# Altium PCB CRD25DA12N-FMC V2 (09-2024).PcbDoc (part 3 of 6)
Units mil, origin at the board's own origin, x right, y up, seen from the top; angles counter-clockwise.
Board outline 8000 x 8000 mil, 6 copper layers (Top Layer, Layer 2, Layer 3, Layer 4, Layer 5, Bottom Layer), stack 91 mil thick; 602 components, 333 nets, 1670 pads, 639 vias.
Unrouted connection lines stored in the file: 1.
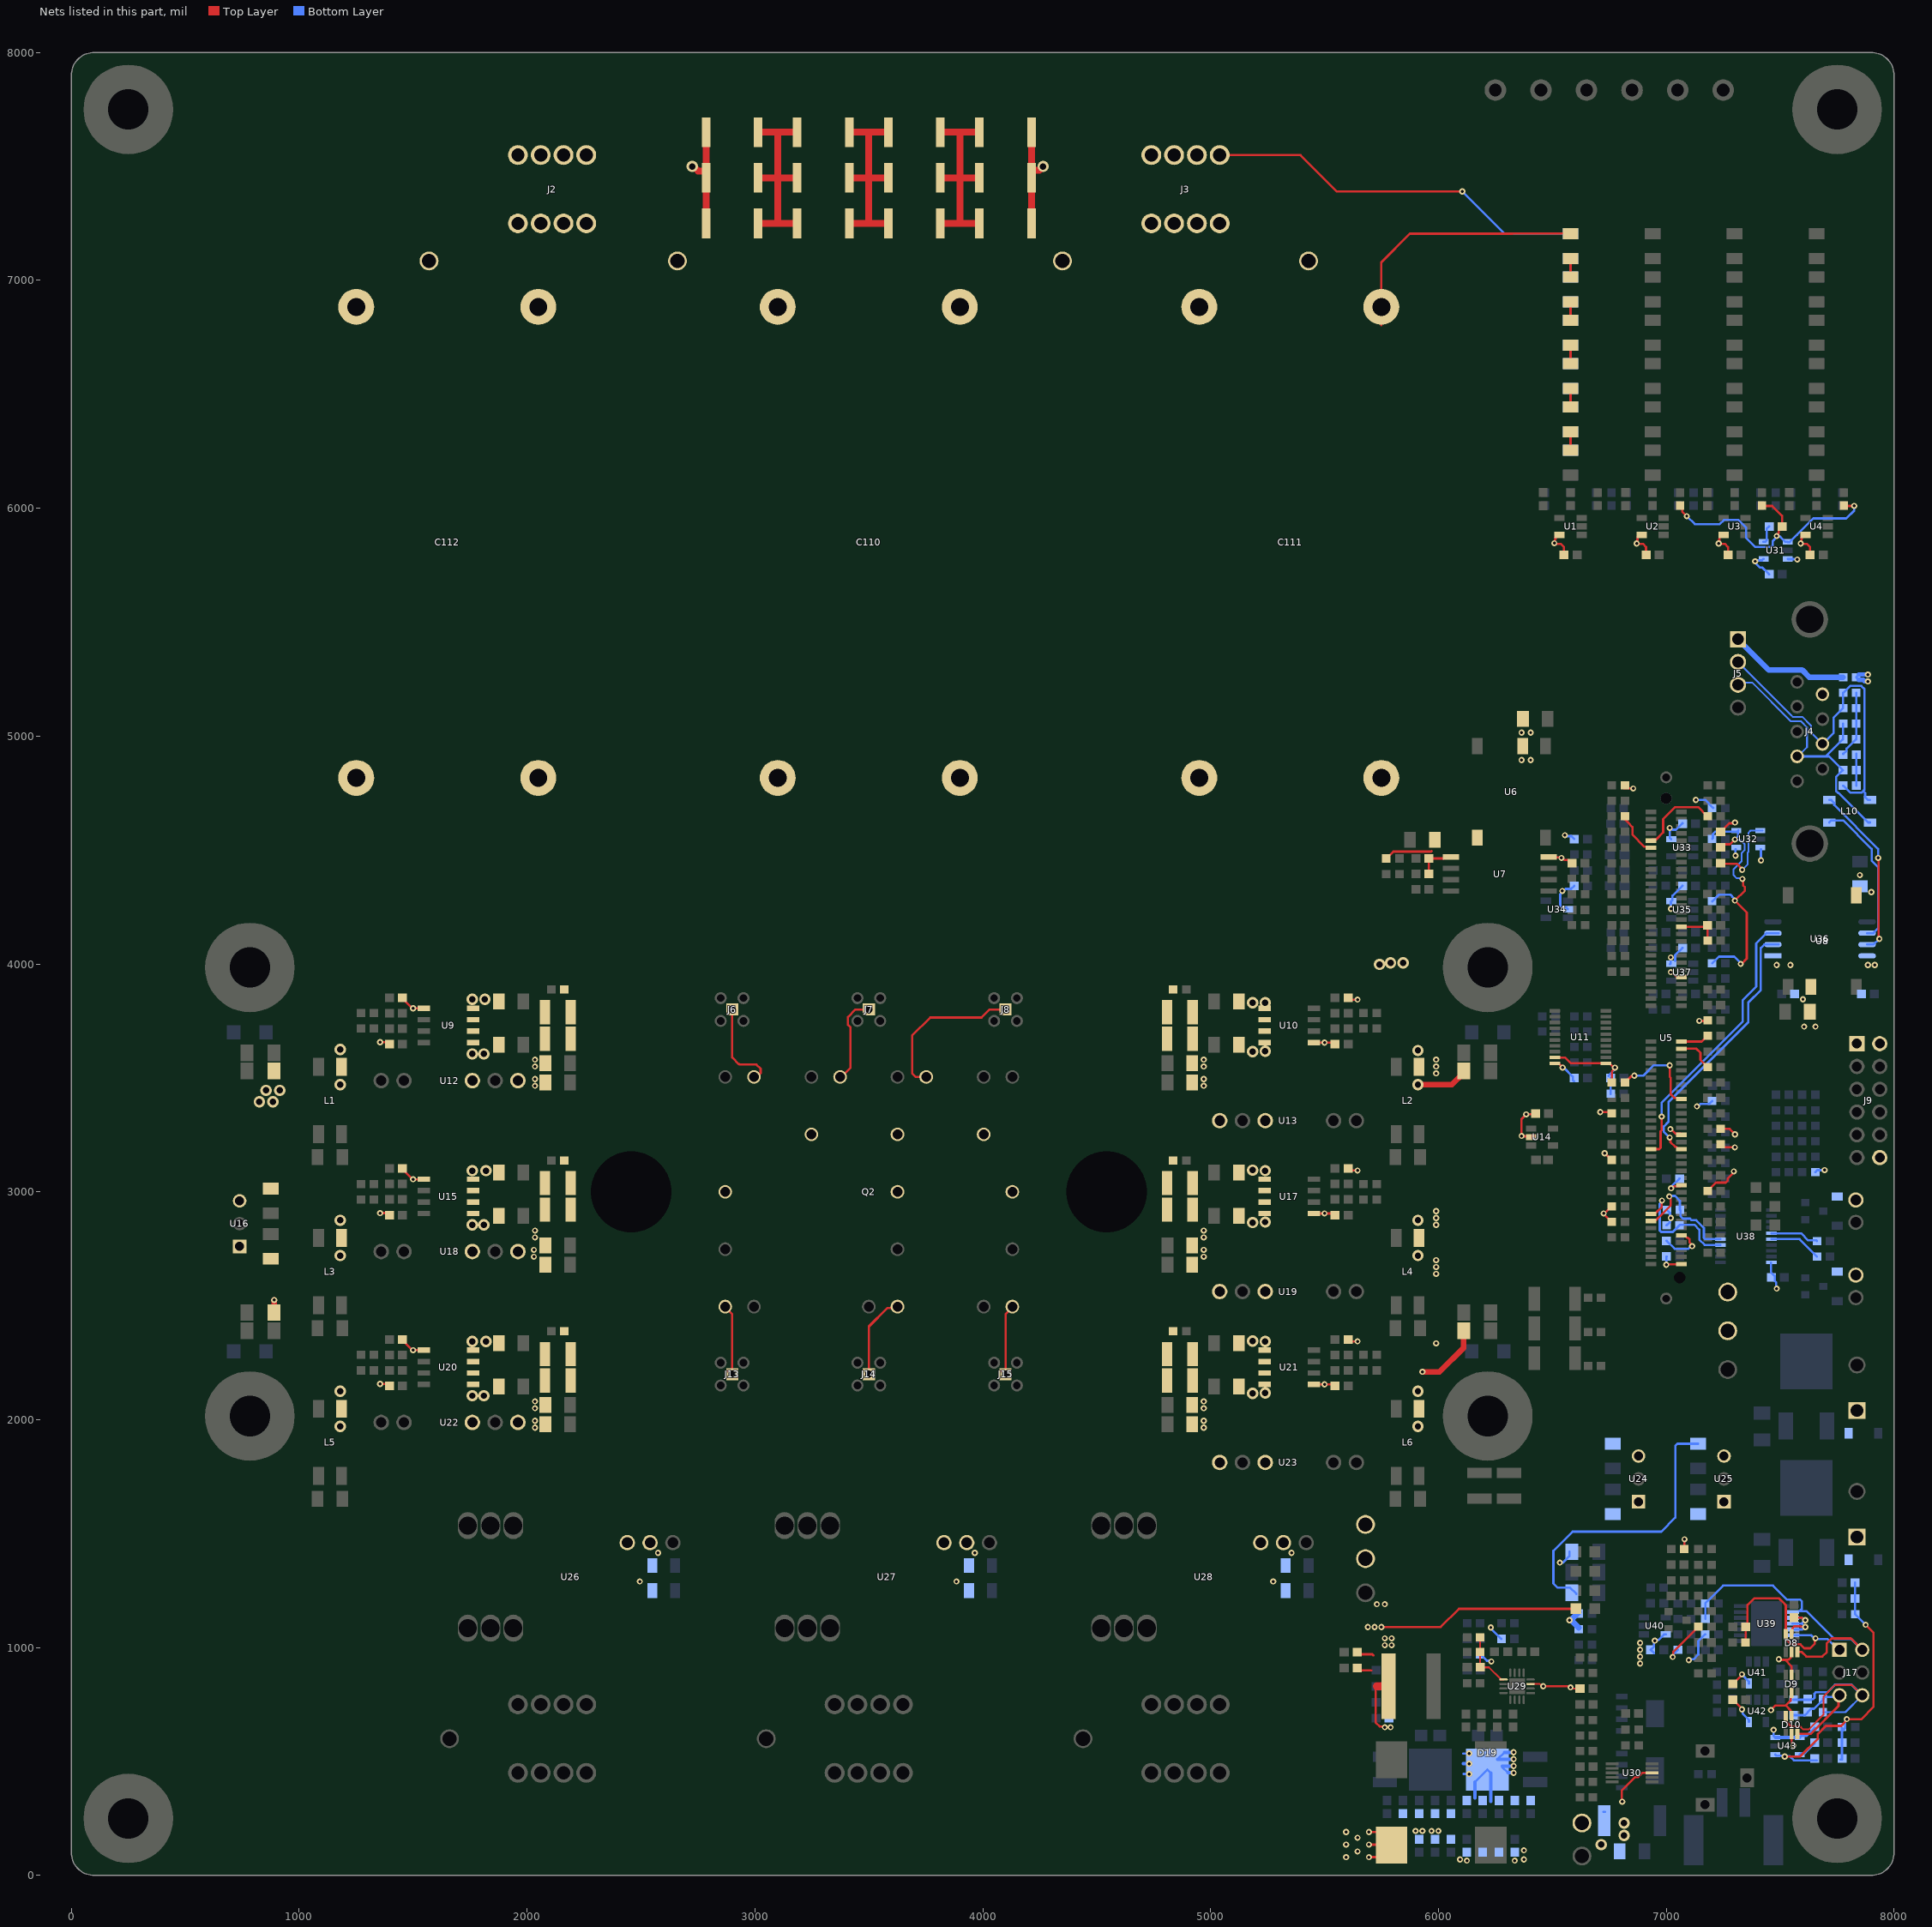
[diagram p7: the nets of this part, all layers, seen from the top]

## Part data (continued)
R91: library part CMP-06022-000547-2, "THERMISTOR NTC 10KOHM 3380K 0603", Case Code (Imperial)=0603, Case Code (Metric)=1608, Manufacturer=MURATA, Max Operating Temperature=150°C, Min Operating Temperature=-40°C
R92 R96 R101 R107 R109 R110 R111 R112 R136 R148 R153 R239 R240: "RES SMD 20K OHM 1% 1/10W 0603", Case Code (Imperial)=0603, Case Code (Metric)=1608, Manufacturer="VISHAY DALE", Max Operating Temperature=155°C, Max Power Dissipation=100mW, Min Operating Temperature=-55°C, Package Quantity=5000, Power Rating=0.1W, Resistance=20kΩ, Resistance Tolerance=1%, Resistor Type="Thick Film", Temperature Coefficient=100ppm/°C, Voltage Rating=75V
R113 R117 R125: "RES SMD 165 OHM 1% 3/4W 2010", Manufacturer=VISHAY, Package=2010, Power=0.75W
R137 R146 R150 R152 R154 R214 R215 R216 R217 R218 R219 R275: "RES 100K OHM 1% 1/10W 0603", Case Code (Imperial)=0603, Case Code (Metric)=1608, Manufacturer=YAGEO, Max Operating Temperature=155°C, Max Power Dissipation=100mW, Min Operating Temperature=-55°C, Power Rating=0.1W, Resistance=100kΩ, Resistance Tolerance=1%, Resistor Type="Thick Film", Supplier Part Number 1=3697448, Temperature Coefficient=100ppm/°C, Voltage Rating=50V, Working Voltage=75V
R140: "RES 20 OHM 5% 1/10W 0603", Case Code (Imperial)=0603, Case Code (Metric)=1608, Manufacturer=YAGEO, Max Operating Temperature=155°C, Max Power Dissipation=100mW, Min Operating Temperature=-55°C, Package Quantity=1, Power Rating=0.1W, Resistance=20Ω, Resistance Tolerance=5%, Resistor Type="Thick Film", Supplier Part Number 1=4144481, Temperature Coefficient=100ppm/°C, Voltage Rating=75V, Voltage Rating (DC)=50V
R143 R249: "RES 470K OHM 1% 1/10W 0603", Case Code (Imperial)=0603, Case Code (Metric)=1608, Manufacturer=YAGEO, Max Operating Temperature=155°C, Max Power Dissipation=100mW, Min Operating Temperature=-55°C, Package Quantity=1, Power Rating=0.1W, Resistance=470kΩ, Resistance Tolerance=1%, Resistor Type="Thick Film", Supplier Part Number 1=4599155, Temperature Coefficient=100ppm/°C, Voltage Rating=50V
R144: "RES SMD 71.5KOHM 0.5% 1/10W 0603", Case Code (Imperial)=0603, Case Code (Metric)=1608, Manufacturer=YAGEO, Max Operating Temperature=155°C, Max Power Dissipation=0.1W, Min Operating Temperature=-55°C, Package Quantity=5000, Resistance=71.5kΩ, Supplier Part Number 1=3077636, Temperature Coefficient=50ppm/°C, Tolerance=0.5%, Voltage Rating (DC)=50V
R145: "RES SMD 49.9K OHM 1% 1/10W 0603", Case Code (Imperial)=0603, Case Code (Metric)=1608, Manufacturer=YAGEO, Max Operating Temperature=125°C, Max Power Dissipation=100mW, Min Operating Temperature=-55°C, Power Rating=0.1W, Resistance=49.9kΩ, Supplier Part Number 1=3100550, Temperature Coefficient=50ppm/°C, Tolerance=1%, Voltage Rating=75V, Voltage Rating (DC)=50V
R147: "RES 24.9K OHM 1% 1/10W 0603", Case Code (Imperial)=0603, Case Code (Metric)=1608, Manufacturer=YAGEO, Max Operating Temperature=155°C, Max Power Dissipation=100mW, Min Operating Temperature=-55°C, Package Quantity=1, Power Rating=0.1W, Resistance=24.9kΩ, Supplier Part Number 1=3435880, Temperature Coefficient=100ppm/°C, Tolerance=1%, Voltage Rating=50V
R149: "RES 61.9K OHM 1% 1/10W 0603", Case Code (Imperial)=0603, Case Code (Metric)=1608, Manufacturer=YAGEO, Max Operating Temperature=155°C, Max Power Dissipation=100mW, Min Operating Temperature=-55°C, Package Quantity=5000, Power Rating=0.1W, Resistance=61.9kΩ, Supplier Part Number 1=9857970, Temperature Coefficient=100ppm/°C, Tolerance=1%, Voltage Rating=50V, Working Voltage=75V
R155 R156: "RES 2.7M OHM 5% 1/10W 0603", Case Code (Imperial)=0603, Case Code (Metric)=1608, Manufacturer=YAGEO, Max Operating Temperature=155°C, Max Power Dissipation=100mW, Min Operating Temperature=-55°C, Package Quantity=1, Power Rating=0.1W, Resistance=2.7MΩ, Resistor Type="Thick Film", Temperature Coefficient=100ppm/°C, Tolerance=5%, Voltage Rating=75V, Voltage Rating (DC)=50V
R193 R194 R195 R196: "RES 120 OHM 5% 1/10W 0603", Case Code (Imperial)=0603, Case Code (Metric)=1608, Manufacturer=YAGEO, Max Operating Temperature=155°C, Max Power Dissipation=0.1W, Min Operating Temperature=-55°C, Package Quantity=1, Power Rating=100mW, Resistance Tolerance=5%, Resistor Type="Thick Film", Supplier Part Number 1=2424206, Temperature Coefficient=100ppm/°C, Voltage Rating=50V
R199 R204 R210: "RES SMD 1.4K OHM 0.5% 1/10W 0603", Manufacturer=YAGEO, Package=0603, Power=0.1W
R200 R205 R211: "RES 7.15K OHM 1% 1/10W 0603", Case Code (Imperial)=0603, Case Code (Metric)=1608, Manufacturer=STACKPOLE, Max Operating Temperature=155°C, Max Power Dissipation=100mW, Min Operating Temperature=-55°C, Power Rating=0.1W, Resistance=7.15kΩ, Resistor Type="Thick Film", Temperature Coefficient=100ppm/°C, Tolerance=1%
R201: "RES SMD 4.02KOHM 0.1% 1/10W 0603", Case Code (Imperial)=0603, Case Code (Metric)=1608, Manufacturer=PANASONIC, Manufacturer Part Number=ERA-3AEB4021V, Max Operating Temperature=155°C, Min Operating Temperature=-55°C, Package Quantity=1, Power=0.1W, Resistance=4.02kΩ, Resistance Tolerance=0.1%, Resistor Type="Thin Film", Supplier Part Number 1=7087616, Temperature Coefficient=25ppm/°C, Voltage Rating=75V
R202 R207 R212: "RES SMD 4.02KOHM 0.1% 1/10W 0603", Case Code (Imperial)=0603, Case Code (Metric)=1608, Manufacturer=PANASONIC, Manufacturer Part Number=ERA-3AEB4021V, Max Operating Temperature=155°C, Max Power Dissipation=100mW, Min Operating Temperature=-55°C, Package Quantity=1, Power Rating=0.1W, Resistance=4.02kΩ, Resistance Tolerance=0.1%, Resistor Type="Thin Film", Supplier Part Number 1=7087616, Temperature Coefficient=25ppm/°C, Voltage Rating=75V
R203 R208 R213: "RES 7.87K OHM 1% 1/10W 0603", Case Code (Imperial)=0603, Case Code (Metric)=1608, Manufacturer=YAGEO, Max Operating Temperature=155°C, Max Power Dissipation=0.1W, Min Operating Temperature=-55°C, Package Quantity=1, Power Rating=100mW, Resistance=7.87kΩ, Resistor Type="Thick Film", Supplier Part Number 1=49AK2736, Temperature Coefficient=100ppm/°C, Tolerance=1%, Voltage Rating=50V
R247 R253: "RES SMD 3.9K OHM 1% 1/10W 0603", Case Code (Imperial)=0603, Case Code (Metric)=1608, Manufacturer=PANASONIC, Manufacturer Part Number=ERJ-3EKF3901V, Max Operating Temperature=155°C, Max Power Dissipation=100mW, Min Operating Temperature=-55°C, Package Quantity=1, Power Rating=0.1W, Resistance=3.9kΩ, Resistance Tolerance=1%, Resistor Type="Thick Film", Supplier Part Number 1=1229307, Temperature Coefficient=100ppm/°C, Voltage Rating=75V
R250 R257: "RES SMD 15K OHM 0.5% 1/10W 0603", Case Code (Imperial)=0603, Case Code (Metric)=1608, Manufacturer=PANASONIC, Max Operating Temperature=155°C, Max Power Dissipation=100mW, Min Operating Temperature=-55°C, Package Quantity=5000, Power Rating=0.1W, Ratings=AEC-Q200, Resistance=15kΩ, Resistance Tolerance=0.5%, Resistor Type="Thin Film", Supplier Part Number 1=P15KBLCT-ND, Temperature Coefficient=25ppm/°C, Voltage Rating=75V
R254: "RES SMD 22.6KOHM 0.5% 1/10W 0603", Case Code (Imperial)=0603, Case Code (Metric)=1608, Manufacturer=YAGEO, Max Operating Temperature=155°C, Max Power Dissipation=0.1W, Min Operating Temperature=-55°C, Package Quantity=5000, Resistance=22.6kΩ, Supplier Part Number 1=311-2487-1-ND, Temperature Coefficient=50ppm/°C, Tolerance=0.5%, Voltage Rating (DC)=50V
R259: "RES SMD 34.8KOHM 0.5% 1/10W 0603", Case Code (Imperial)=0603, Case Code (Metric)=1608, Manufacturer=YAGEO, Max Operating Temperature=155°C, Max Power Dissipation=100mW, Min Operating Temperature=-55°C, Package Quantity=5000, Power Rating=0.1W, Resistance=34.8kΩ, Supplier Part Number 1=311-2545-1-ND, Temperature Coefficient=50ppm/°C, Tolerance=0.5%, Voltage Rating=75V, Voltage Rating (DC)=50V
R262: "RES SMD 5.36KOHM 0.1% 1/10W 0603", Case Code (Imperial)=0603, Case Code (Metric)=1608, Manufacturer=YAGEO, Max Operating Temperature=155°C, Max Power Dissipation=100mW, Min Operating Temperature=-55°C, Package Quantity=5000, Power Rating=0.1W, Resistance=5.36kΩ, Supplier Part Number 1=YAG1697CT-ND, Temperature Coefficient=25ppm/°C, Tolerance=0.1%, Voltage Rating=75V, Voltage Rating (DC)=50V
R264 R267 R268 R271: "RES SMD 12.1K OHM 0.1% 1/5W 0603", Case Code (Imperial)=0603, Case Code (Metric)=1608, Manufacturer=PANASONIC, Max Operating Temperature=155°C, Max Power Dissipation=0.2W, Min Operating Temperature=-55°C, Resistance=12.1kΩ, Resistor Type="Thick Film", Supplier Part Number 1=68AC5970, Temperature Coefficient=50ppm/°C, Tolerance=0.1%
R265 R269: "RES 47K OHM 1% 1/10W 0603", Case Code (Imperial)=0603, Case Code (Metric)=1608, Manufacturer=YAGEO, Max Operating Temperature=155°C, Max Power Dissipation=100mW, Min Operating Temperature=-55°C, Package Quantity=1, Power Rating=0.1W, Resistance=47kΩ, Resistance Tolerance=1%, Resistor Type="Thick Film", Supplier Part Number 1=6616189, Temperature Coefficient=100ppm/°C, Voltage Rating=50V
R273 R274: "RES SMD 10 OHM 1% 3/4W 1210", Case Code (Imperial)=1210, Case Code (Metric)=3225, Manufacturer=VISHAY, Max Operating Temperature=155°C, Max Power Dissipation=750mW, Min Operating Temperature=-55°C, Package Quantity=10, Power Rating=0.75W, Ratings=AEC-Q200, Resistance=10Ω, Supplier Part Number 1=71-CRCW121010R0FKEAH, Temperature Coefficient=100ppm/°C, Tolerance=1%, Voltage Rating=200V
R276: "RES 0.01 OHM 1% 2W 2512", Case Code (Imperial)=2512, Case Code (Metric)=6432, Manufacturer=YAGEO, Max Operating Temperature=170°C, Max Power Dissipation=2W, Min Operating Temperature=-55°C, Resistance=10mΩ, Resistor Type="Metal Film", Supplier Part Number 1=1995902P, Temperature Coefficient=50ppm/°C, Tolerance=1%
TP1 TP2 TP5 TP6 TP8 TP9 TP14: library part CMP-1672-00002-4, "PC TEST POINT MULTIPURPOSE RED", Colour=Red, Manufacturer=KEYSTONE, Package=N/A, Package Quantity=100
TP3 TP4 TP7 TP10 TP15: library part CMP-1672-00003-4, "PC TEST POINT MULTIPURPOSE BLACK", Colour=Black, Manufacturer=KEYSTONE, Package=N/A, Package Quantity=100
TP11 TP12 TP13: library part CMP-1672-00004-4, "PC TEST POINT MULTIPURPOSE WHITE", Colour=White, Manufacturer=KEYSTONE, Package=N/A, Package Quantity=100
U1 U2 U3 U4 U33 U35 U37 U40 U41 U42: library part CMP-0384-02059-2, "IC OPAMP GP 1 CIRCUIT TSOT23-5", Amplifiers Per Package=1, Generic Part Number=AD8615, Input Bias Current=200fA, Input Offset Voltage=80uV, Manufacturer="ANALOG DEVICES", Package=TSOT-23-5
U5: "EVAL BOARD FOR TMS320F280039C", Manufacturer="TEXAS INSTRUMENTS", Package=N/A, Supplier Part Number 1=595-TMDSCNCD280039C
U6 U8: "DC DC CONVERTER 5V 1W", Case/Package=SMD/SMT, Current - Output 1=200mA, Isolation Voltage=2kV, Manufacturer=RECOM, Max Input Voltage=3.63V, Max Operating Temperature=100°C, Max Output Power=1W, Max Output Voltage=5V, Min Input Voltage=2.97V, Min Operating Temperature=-40°C, Package=8-SMD, Supplier Part Number 1=945-R1SE-3.305/H2-RCT-ND
U7: library part CMP-04893-000001-1, "IC ISOLATION 8SOIC", Ambient Temperature Range High=+125°C, Ambient Temperature Range Low=-40°C, Input Bias Current=0.0035uA, Input Offset Voltage=-1.1mV, Manufacturer="TEXAS INSTRUMENTS", Max Junction Temp=+150°C, Max Supply Voltage=5.5V, Min Supply Voltage=3V, Nominal Supply Current=1.3-7100uA, Package=DWV0008A, Temperature="-55°C to +125°C", Temperature Range Low=-55°C
U9 U10 U15 U17 U20 U21: "5A/5A, 3-KVRMS SINGLE-CHANNEL IS", Manufacturer="TEXAS INSTRUMENTS", Max Operating Temperature=125°C, Mfr_Name="Texas Instruments", Min Operating Temperature=-40°C, Package=8-SOIC, Supplier Part Number 1=296-47508-ND, Working Voltage=990V
U11 U38: library part CMP-0440-01163-3, "IC BUF NON-INVERT 5.5V 20TSSOP", F @ Nom Voltage(Max)(Mhz)=110, Generic Part Number=SN74LV541AT, ICC @ Nom Voltage(Max)(mA)=0.02, Manufacturer="TEXAS INSTRUMENTS", Operating Temperature Range(C)="-40 to 125", Package=20-TSSOP, Rating=Catalog, tpd @ Nom Voltage(Max)(ns)=7.9, Voltage(Nom)(V)=5
U12 U13 U18 U19 U22 U23: "DC DC CONVERTER 15V -3V 1.7W", Manufacturer=MURATA, Package=7-SIP, Supplier Part Number 1=580-MGJ2D121503SC
U14 U34: "IC OPAMP GP 1 CIRCUIT SOT23-5", Case/Package=SOT-23-5, Manufacturer=MICROCHIP
U16 U25: "DC DC CONVERTER 5V 5W", Case/Package=SIP, Current - Output 1=1A, Manufacturer=RECOM, Max Input Voltage=28V, Max Operating Temperature=85°C, Max Output Voltage=5V, Max Power Dissipation=5W, Min Input Voltage=8V, Min Operating Temperature=-40°C, Package=3-SIP, Package Quantity=42, Supplier Part Number 1=1446013
U24: "DC DC CONVERTER 3.3V 3W", Case/Package=SIP, Manufacturer=RECOM, Max Input Voltage=28V, Max Operating Temperature=85°C, Max Output Current=1A, Max Output Power=3.3W, Max Output Voltage=3.3V, Max Power Dissipation=3W, Min Input Voltage=8V, Min Input Voltage (DC)=7V, Min Operating Temperature=-40°C, Package=3-SIP, Supplier Part Number 1=9176626
U26 U27 U28: "SENSOR CURRENT HALL 50A AC/DC", Case/Package=Module, Current Rating=50A, Frequency=200kHz, Manufacturer=LEM, Max Operating Temperature=85°C, Max Supply Current=35mA, Min Operating Temperature=-25°C, Operating Supply Voltage=15V, Package=N/A, Package Quantity=12, Secondary Current=25mA, Supplier Part Number 1=44W8442
U29: "IC REG MULT CONFG ADJ 6.5A 16QFN", Manufacturer="TEXAS INSTRUMENTS", Package=16-WFQFN, Supplier Part Number 1=595-LM5157QRTERQ1
U30: "IC SURGE SUPPRESSION ADJ 10MSOP", Manufacturer="ANALOG DEVICES", Package=10-MSOP, Supplier Part Number 1=505-LTC4368IMS-2#PBF-ND
U31 U32 U43: "AUTOMOTIVE LOW-DRIFT, LOW-POWER,", Manufacturer="TEXAS INSTRUMENTS", Package=TSOT-23-5, Supplier Part Number 1=595-REF2033QDDCRQ1
U36: library part CMP-04872-000086-1, "IC TXRX/ISO FULL 1/1 8SOIC", Manufacturer="TEXAS INSTRUMENTS", Package=8-SOIC
U39: library part CMP-04895-000282-1, "IC POWER 2 CIRCUIT 14HTSSOP", Manufacturer="TEXAS INSTRUMENTS", Package=14-PowerTSSOP

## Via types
v1: diameter 27, hole 13, Top Layer to Bottom Layer, tented both sides, 543 vias
v2: diameter 50, hole 28, Top Layer to Bottom Layer, tented both sides, 76 vias
v3: diameter 19.68, hole 7.87, Top Layer to Bottom Layer, tented top, 15 vias
v4: diameter 19.68, hole 7.87, Top Layer to Bottom Layer, tented both sides, 5 vias

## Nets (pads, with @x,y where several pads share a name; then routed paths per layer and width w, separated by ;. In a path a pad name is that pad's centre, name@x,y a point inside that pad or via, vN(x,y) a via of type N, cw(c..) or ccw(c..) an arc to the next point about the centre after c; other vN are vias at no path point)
+1.65V_I: C16.1 U32.1 | length 349
  Top Layer w10: C16.1@7238.58,4442 7240.58,4440 7310,4440 7333.21,4416.79 v1(7333.21,4413.21)
  Bottom Layer w8: v1(7333.21,4413.21) 7357.5,4437.5 7357.5,4488.19 7361.5,4492.18 7361.5,4576.5 7370.4,4585.4 U32.1@7423.15,4585.4
+1.65V_R: C161.1 C165.1 C181.1 C183.1 C184.1 R252.1 R272.1 U43.1 | length 1476.3
  Top Layer w10: v1(7520,521.49) 7586.8,521.49 7665,599.69 7665,620.31 7700.64,655.94 7767.72,655.94 7775.01,663.23 7775.01,663.81 7792.41,681.2 v1(7792.41,685.8) 7793.21,685 7820.91,685 7855,685 7910,740 7910,1065 v1(7875,1100)
  Bottom Layer w10: U43.1@7478.7,530.2 7484.15,524.74 7516.75,524.74 v1(7520,521.49) 7521.6,523.09 7541.91,523.09 7560,505 C184.1@7660.37,505 ; C183.1@7765.47,508 7771.42,508 C183.1@7771.42,513 7771.42,577.05 7770.47,578 7771.42,578 C181.1@7771.42,583 7771.42,634 ; R272.1@7771.38,647 7771.42,646.96 7771.42,634 ; v1(7792.41,685.8) 7792.41,681.2 7785.24,674.03 7785.24,646.96 7772.28,634 7771.42,634 ; C161.1@7828.58,1285 C165.1@7828.58,1215 C165.1@7828.58,1215 R252.1@7828.62,1146 7829.53,1146 7875,1100.53 v1(7875,1100)
+1.65V_V: C5.1 R40.2 R42.2 R44.2 U31.1 | length 1265.4
  Top Layer w10: R40.2@7060,6011.38 7069.85,6001.53 7069.85,5985.15 v1(7090,5965) ; R42.2@7420,6011.38 7421.38,6010 7465,6010 7508.58,5966.42 C5.1@7508.58,5920 7507.63,5920 7493.76,5906.14 7493.76,5891.72 7484.64,5882.6 v1(7484.64,5878) ; R44.2@7780,6011.38 7781.38,6010 v1(7825,6010)
  Bottom Layer w10: v1(7090,5965) 7125,5930 7234.54,5930 7253.04,5948.5 7316.81,5948.5 7350.91,5914.39 7350.91,5869.09 7390.41,5829.59 7459.9,5829.59 7467.25,5836.94 7467.25,5856.01 7484.64,5873.4 v1(7484.64,5878) 7487.9,5874.75 7500.96,5874.75 7523.31,5852.4 U31.1@7533.15,5852.4 ; U31.1@7533.15,5851.2 7541.79,5851.2 7574.09,5883.5 7645.59,5955 7790,5955 7825,5990 v1(7825,6010)
+3.3V: C6.1 C7.1 C8.1 C9.1 C10.1 C15.1 C31.1 C45.1 C100.1 C102.1 C123.1 C126.1 C135.1 C136.1 C140.1 C142.1 C155.1 C170.1 J9.1 R45.2 R71.2 R86.2 R89.2 R90.2 R92.2 R102.2 R107.2 R109.2 R135.2 R197.2 R223.2 R235.2 R239.2 R240.2 R245.1 R257.2 TP5.1 U1.5 U2.5 U3.5 U4.5 U6.2 U7.8 U8.2 U14.2 U24.3 U33.5 U34.2 U35.5 U36.1 U37.5 U40.5 U41.5 U42.5 | length 2896
  Top Layer w10: U14.2@6406.77,3242 6405.27,3243.5 6366.5,3243.5 v1(6365,3245) 6365,3319.69 6385,3339.69 v1(6385,3340) 6422.42,3340 C45.1@6426.42,3344 ; U7.8@6484.57,4470 6487.07,4467.5 6537.5,4467.5 v1(6540,4465) 6544.6,4465 6553.74,4455.86 6567.56,4455.86 C15.1@6581.42,4442 ; U1.5@6531.77,5882.6 6522.91,5882.6 6514.13,5873.82 6514.13,5864.96 6511.83,5862.66 6511.83,5849.68 v1(6508.58,5846.42) 6511.14,5843.86 6537.56,5843.86 6551.42,5830 C6.1@6551.42,5795 ; v1(6710,3350) 6755.38,3350 R86.2@6761.38,3344 ; v1(6729.42,3169.05) 6731.43,3169.05 6760.47,3140 R92.2@6761.38,3140 ; R109.2@6761.38,2868 6760.47,2868 6725,2903.47 v1(6725,2905) 6729.47,2905 6760.47,2936 R107.2@6761.38,2936 ; R45.2@6815,4770 v1(6855,4770) ; U2.5@6891.77,5882.6 6882.91,5882.6 6874.13,5873.82 6874.13,5864.96 6873.25,5864.08 6873.25,5848.25 v1(6870,5845) 6871.14,5843.86 6897.56,5843.86 6911.42,5830 C7.1@6911.42,5795 ; R135.2@7078.62,1432 7080,1433.38 v1(7080,1475) ; v1(7145,3750) 7179.38,3750 R71.2@7181.38,3752 ; R102.2@7181.38,3004 7182.28,3004 7218.28,3040 7260.81,3040 7269.39,3048.58 7269.39,3057.8 7296.6,3085.02 v1(7296.6,3089.62) ; R90.2@7238.62,3208 7251.58,3195.04 7300.94,3195.04 v1(7300.98,3195) ; R89.2@7238.62,3276 7277.9,3276 v1(7301.9,3252) ; U3.5@7251.77,5882.6 7242.91,5882.6 7234.13,5873.82 7234.13,5864.96 7233.25,5864.08 7233.25,5848.25 v1(7230,5845) 7231.14,5843.86 7257.56,5843.86 7271.42,5830 C8.1@7271.42,5795 ; C102.1@7291.42,771 7292.37,771 7332.36,731.01 v1(7332.36,728.64) ; C100.1@7291.42,840 7292.37,840 7332.36,879.99 v1(7332.36,882.36) ; U4.5@7611.77,5882.6 7602.91,5882.6 7594.13,5873.82 7594.13,5864.96 7593.25,5864.08 7593.25,5848.25 v1(7590,5845) 7591.14,5843.86 7617.56,5843.86 7631.42,5830 C9.1@7631.42,5795
  Bottom Layer w10: v1(6533.01,1372.78) 6533.48,1373.25 6547.07,1373.25 6575,1401.18 R245.1@6575,1420 ; v1(6544.02,4320) 6544.02,4315.4 6534.59,4305.97 6534.59,4254.64 6540.45,4248.78 6559.45,4248.78 U34.2@6568.23,4240 ; v1@6545,4320 6549.6,4320 6558.74,4329.14 6582.56,4329.14 C136.1@6596.42,4343 ; v1(6555,4565) 6559.6,4565 6563.78,4560.82 6583.6,4560.82 C126.1@6596.42,4548 ; C170.1@6931.42,990 C170.1@6932.37,990 ; C170.1@6946.24,976.14 C170.1@6932.37,990 ; v1(6950,1030) 6950,1025.4 6946.24,1021.64 6946.24,1003.86 C170.1@6932.37,990 ; 6965.02,1033.25 6989.37,1057.6 U40.5@6998.23,1057.6 ; R240.2@7001.38,2853 7002.28,2853 7015.24,2865.96 7015.24,2875.64 7020,2880.4 v1(7020,2885) 7020,2889.6 7016.62,2892.98 7016.62,2907.04 7015.91,2907.76 7015,2907.76 R239.2@7002.76,2920 ; U37.5@7016.42,3999.05 7019.81,4002.44 v1(7019.81,4028.66) ; v1(7020.56,4241.93) 7020.56,4272.68 7019.81,4273.44 U35.5@7021.77,4275.4 7027.47,4281.1 7027.47,4300 7070.47,4343 C135.1@7071.42,4343 ; U33.5@7021.77,4547.4 7015.1,4554.07 v1(7015.1,4596.7) 7019.7,4596.7 7027.41,4589 7042.47,4589 7070.47,4617 C123.1@7071.42,4617 ; U37.5@7039.41,4013.18 7039.41,4038.94 7070.47,4070 C140.1@7071.42,4070 ; v1(7099.02,944.96) 7102.27,948.21 7119.21,948.21 7140.61,969.62 7140.61,1028.14 7170.47,1058 R257.2@7171.38,1058 ; v1(7130,4720) 7170.47,4720 7205.47,4685 R197.2@7206.38,4685 ; v1(7135,3375) 7139.6,3375 7149.64,3385.04 7188.42,3385.04 R223.2@7201.38,3398 ; v1(7332.36,728.64) 7335.62,725.38 7335.62,709.38 7362.6,682.4 U42.5@7362.6,673.54 ; v1(7332.36,882.36) 7332.36,880.87 7362.6,850.63 U41.5@7362.6,841.77 ; R235.2@7653.62,3086 7662.62,3095 v1(7695,3095)
  other v1: 7605,3725 7655,3725 7600,3845 7485,3995 7545,3995 6365,4895 6405,4895 6365,5015 6405,5015
+3.3V_I: C13.1 R199.2 R204.2 R210.2 U32.5 | length 1224.7
  Top Layer w10: C13.1@7238.58,4511 7252.44,4524.86 7279.94,4524.86 v1(7300.98,4545.91) ; v1(7326.5,4000) 7330,4000 7353.5,4023.5 7353.5,4225.75 v1(7300.98,4278.27) 7345,4322.29 7345,4337.27 7337.32,4344.95 7337.32,4369.55 v1(7334.06,4372.81)
  Bottom Layer w8: v1(7300.98,4545.91) 7303.4,4543.5 7326.82,4543.5 7343.5,4526.82 7343.5,4499.64 7331.5,4487.65 7331.5,4451.81 7295,4415.31 7295,4390 7308.94,4376.06 v1@7330.81,4376.06
  Bottom Layer w10: R210.2@7201.38,4003 7202.28,4003 7231.24,4031.96 7298.04,4031.96 7326.5,4003.5 v1(7326.5,4000) ; R204.2@7201.38,4275 7202.28,4275 7231.24,4303.96 7282.04,4303.96 7289.11,4296.88 7289.11,4294.74 7300.98,4282.87 v1(7300.98,4278.27) ; R199.2@7201.38,4548 7205,4551.62 7205,4570 7215,4580 7311.45,4580 U32.5@7315,4583.55 ; v1(7300.98,4545.91) 7300.98,4545.98 7315,4560 U32.5@7315,4583.55 ; U32.5@7316.85,4585.4 U32.5@7315,4583.55 ; v1@7330.81,4376.06 v1(7334.06,4372.81)
+3.3V_R: C182.1 U43.5 | length 86.2
  Bottom Layer w10: U43.5@7585,530.2 7591.81,537.01 7609.48,537.01 7650.47,578 C182.1@7651.42,578
+3.3V_V: C117.1 U31.5 | length 82
  Bottom Layer w10: U31.5@7426.85,5852.4 7434.01,5852.4 7440.82,5859.21 7440.82,5909.4 C117.1@7451.42,5920
+5V: C11.1 C27.1 C39.1 C50.1 C62.1 C72.1 C82.1 C118.1 C147.1 C150.1 C151.1 C152.1 C153.1 C154.1 C180.1 J9.2 R248.1 TP6.1 U5.48 U5.84 U5.98 U5.112 U5.120 U10.1 U11.20 U17.1 U21.1 U25.3 U31.3 U31.4 U32.3 U32.4 U38.20 U43.3 U43.4 | length 3053.7
  Top Layer w10: U21.1@5453.27,2155 5544.42,2155 C82.1@5551.42,2148 ; U17.1@5453.27,2905 5544.42,2905 C62.1@5551.42,2898 ; U10.1@5453.27,3655 5544.42,3655 C39.1@5551.42,3648 ; C72.1@5608.58,2352 5617.08,2343.5 v1(5645,2343.5) ; C50.1@5608.58,3102 5617.08,3093.5 v1(5645,3093.5) ; C27.1@5608.58,3852 5617.08,3843.5 v1(5645,3843.5) ; U11.20@6510.59,3563.82 6526.34,3563.82 6536.9,3553.25 6546.75,3553.25 v1@6550,3550 ; v1(7000,2680) 7001.44,2681.44 7065.49,2681.44 U5.120@7066.93,2682.87 ; v1(7018,3275) 7020.61,3275 7040.94,3254.67 7042.45,3254.67 7062.09,3254.65 U5.84@7066.93,3249.8 ; v1(7019.81,3964.12) 7024.41,3964.12 7040.97,3947.56 7062.09,3947.56 U5.48@7066.93,3942.72 ; v1(7021.2,3015.64) 7025.8,3015.64 7034.65,3024.49 7062.09,3024.49 U5.98@7066.93,3029.33 ; U5.112@7066.93,2808.86 7080.71,2808.86 7091.36,2798.2 7095.11,2798.2 7101.55,2791.76 7101.55,2777.96 7113.3,2766.21 v1(7113.3,2761.61) ; C11.1@7238.58,4580 7239.53,4580 7276.99,4617.46 7298.64,4617.46 v1(7301.89,4620.71)
  Bottom Layer w10: v1(6545,3545) 6548.25,3541.75 6553.73,3541.75 6590,3505.47 6590,3490 C147.1@6595,3485 ; R248.1@6605.54,1235 6577.04,1263.5 6521.93,1263.5 6504.51,1280.93 6504.51,1424.51 6588.5,1508.5 6978.5,1508.5 7040,1570 7040,1885 7049.19,1894.19 C154.1@7140,1894.19 ; v1(7000,2680) 7000,2714.58 C152.1@7001.42,2716 ; C151.1@7001.42,2785 7002.37,2785 7037.37,2750 7097.08,2750 7108.7,2761.61 v1(7113.3,2761.61) ; v1(7021.2,3015.64) 7024.45,3018.89 7024.45,3024.82 7057.63,3058 C150.1@7058.58,3058 ; v1(7304,4475) 7304,4503.79 U32.4@7305,4503.79 ; v1(7390,5767) 7393.25,5763.75 7393.25,5757.66 7410.61,5740.31 7420.17,5740.31 7450.47,5710 C118.1@7451.42,5710 ; v1@7393.5,5763.5 7400.79,5770.79 7420.04,5770.79 U31.4@7426.85,5777.6 ; U32.3@7415,4503.79 7415.79,4503.79 v1(7415.79,4454.48) ; U38.20@7459.41,2688.82 7459.41,2647.05 7476.24,2630.22 7476.24,2608.36 7481.75,2602.85 7481.75,2578.25 v1(7485,2575) ; v1(7471.28,638.72) 7471.28,611.81 7478.09,605 U43.3@7478.7,605 ; U31.3@7533.15,5777.6 7534.45,5776.3 7573.7,5776.3 v1(7575,5775) ; U43.4@7588.19,605 U43.4@7585,605 7591.81,611.81 7615.28,611.81 7650.47,647 C180.1@7651.42,647
  Bottom Layer w15: U43.3@7478.7,605 U43.4@7585,605
  other v1: 5500,2155 5990,2335 5990,2640 5990,2670 5990,2700 5990,2855 5990,2885 5500,2905 5990,2915 5990,3520 5990,3550 5990,3580 5500,3655
+5V_ALT: C26.1 C38.1 C49.1 C56.1 C61.1 C71.1 C81.1 U9.1 U15.1 U16.3 U20.1 | length 475.4
  Top Layer w10: v1(1355,2156.5) 1382.92,2156.5 C81.1@1391.42,2148 ; v1(1355,2906.5) 1382.92,2906.5 C61.1@1391.42,2898 ; v1(1355,3656.5) 1382.92,3656.5 C38.1@1391.42,3648 ; C71.1@1448.58,2352 1449.53,2352 1495,2306.53 1495,2305 U20.1@1546.73,2305 ; C49.1@1448.58,3102 1449.53,3102 1495,3056.53 1495,3055 U15.1@1546.73,3055 ; C26.1@1448.58,3852 1449.53,3852 1495,3806.53 1495,3805 U9.1@1546.73,3805
  other v1: 1500,2305 1500,3055 1500,3805
+5V_ISO: C128.1 C141.1 J4.9 R192.2 U8.5 U36.8 | length 115.2
  Bottom Layer w10: R192.2@7844.63,5246.99 R192.2@7833.62,5258 R192.2@7845.62,5270
  Bottom Layer w20: R192.2@7844.63,5246.99 7864.36,5246.99 7870.01,5241.34 7883.66,5241.34 v1(7885,5240) ; R192.2@7845.62,5270 v1(7885,5270)
  other v1: 7885,3995 7915,3995 7900,4315 7850,4390
+5V_ISO_BUF: J5.1 R192.1 | length 530.8
  Bottom Layer w25: J5.1@7315,5425 7450,5290 7552.18,5290 7552.48,5290.3 7595.71,5290.3 7628.01,5258 R192.1@7776.38,5258
+5V_NTC: C12.1 C14.1 C17.1 R53.2 U6.5 U7.1 | length 380.6
  Top Layer w10: R53.2@5771.38,4463 5772.28,4463 5802.15,4492.86 5967.86,4492.86 5970,4495 ; C14.1@5957.63,4463 C14.1@5958.58,4463 ; C17.1@5958.58,4395 C14.1@5958.58,4463 ; U7.1@6055.43,4470 6031.81,4470 6024.81,4463 C14.1@5958.58,4463
+12V: C64.1 C97.1 C99.1 C101.1 C156.1 C157.1 C172.1 C175.1 C178.1 C179.1 C203.1 D13.1 D14.1 D17.1 D18.1 J9.12 J10.2 J11.2 J12.1 J16.1 L1.1 L2.1 L3.1 L4.1 L5.1 L6.1 L7.1 R80.1 R81.1 R115.1 R119.1 R259.2 R276.2 TP14.1 U16.1 U24.1 U25.1 U29.3 U30.8 | length 1493.4
  Top Layer w8: U29.3@6404.23,839.84 6445.02,839.84 6454.86,830 6575.1,830 6584.77,820.33 6620.09,820.33 C101.1@6621.42,819
  Top Layer w10: C99.1@5643.58,900 5705,900 ; C97.1@5643.58,970 5710,970 5715,965 ; 5730.86,830 5725,824.14 5725,670 5741.75,653.25 5758.25,653.25 v1@5760,655 ; R81.1@6110.9,3522.08 R81.1@6110.9,3530 ; v1(6806.5,323.5) 6805,325 6805,373.06 6863.39,431.45 6876.45,431.45 6894.84,449.84 U30.8@6935.16,449.84
  Top Layer w25: R115.1@889.1,2470 885.21,2473.9 890,2478.69 v1(890,2525) ; v2(5910,3470) 6058.82,3470 R81.1@6110.9,3522.08 ; v1(5930,2210) 6005,2210 6110.9,2315.9 R119.1@6110.9,2390
  Top Layer w35: 5730.86,830 L7.1@5781.57,830
  Bottom Layer w10: v1(6230,1088) 6230,1083.47 6275.47,1038 R259.2@6276.38,1038 ; R276.2@6724.07,278.08 R276.2@6731.14,278.08
  other v1: 5765,650 5790,650 6579.93,825.16 6460,830 5765,1010 5795,1010 5765,1040 5795,1040
  other v2: 6715,135 6815,175 6815,230 1180,1970 5910,1970 1180,2125 5910,2125 1180,2720 5910,2720 1180,2875 5910,2875 825,3395 885,3395 855,3445 915,3445 1180,3470 5910,3620 1180,3625 5742.08,3997.92 5790,4005 5845,4005
+15V: C92.1 C158.1 C159.1 C160.1 C185.2 C186.1 C187.1 C188.1 C189.1 C195.1 C196.1 C197.1 C198.1 D8.2 D8.5 D9.2 D9.5 D10.2 D10.5 D19.1 R141.2 R251.2 R256.2 R261.2 R262.2 TP8.1 U26.8 U27.8 U28.8 U39.10 U39.11 U39.12 | length 1792.9
  Top Layer w10: v1(7028.2,958.5) 7031.16,961.46 7031.16,981.69 7140.47,1091 R141.2@7141.38,1091 ; v1(7459.43,725.36) 7479.79,745.72 7525.11,745.72 ; v1(7494.07,948.46) 7496.54,945.99 7520,945.99 ; D10.2@7550,620.63 7550,582.22 7558,574.22 v1(7558,569.62) ; D10.5@7550,699.37 7546.14,703.23 7546.14,724.69 7525.11,745.72 ; D9.2@7550,800.63 7546.14,796.77 7546.14,766.75 7525.11,745.72 ; D9.5@7550,879.37 7549.98,917.01 7520,946.99 7537.82,946.99 7546.14,955.31 7546.14,976.77 D8.2@7550,980.63 ; D8.5@7550,1059.37 7553.86,1063.23 7553.86,1084.69 7562.18,1093.01 7589.01,1093.01 7590.51,1091.5 7608.5,1091.5 v1(7610,1090) ; C92.1@7560,1131.42 7593.98,1131.42 7605.4,1120 v1(7610,1120)
  Bottom Layer w10: 6108.5,535 v1(6135,535) ; 6110,445 v1(6135,445) ; D19.1@6160,409.06 D19.1@6215,464.06 D19.1@6230,449.06 ; R262.2@6183.62,970 6184.53,970 6212.64,941.89 6228.7,941.89 v1(6231.95,938.64) ; D19.1@6260,510 6259.69,510.31 D19.1@6289.37,540 ; D19.1@6280.47,480 6280.47,474.02 D19.1@6304.49,450 ; v1@6583.73,1123.25 6578.25,1123.25 v1(6575,1120) 6578.25,1116.75 v1@6585.73,1116.75 ; R256.2@6615.47,1087 R256.2@6616.38,1087 ; R251.2@6615.47,1155 R251.2@6616.38,1155 ; v1(7028.2,958.5) 7031.16,961.46 7031.16,970.69 7050.47,990 R261.2@7051.38,990 ; U39.12@7554.17,1079.41 7597.69,1079.41 7608.28,1090 v1(7610,1090) 7595,1105 ; U39.11@7554.17,1105 7595,1105 ; U39.10@7555.91,1128.86 U39.10@7554.17,1130.59 7596.29,1130.59 7606.88,1120 v1(7610,1120) 7595,1105
  Bottom Layer w15: 6110,490 v1(6135,490) ; 6160,340 D19.1@6160,409.06 ; 6230,325 D19.1@6230,449.06 ; D19.1@6260,510 v1(6330,510) ; D19.1@6280.47,480 v1(6330,480) ; D19.1@6289.37,540 v1(6330,540) ; D19.1@6304.49,450 v1(6330,450)
  Bottom Layer w25: v1@6583.73,1123.25 R251.2@6615.47,1155 ; v1@6585.73,1116.75 R256.2@6615.47,1087
  other v1: 6125,65 6335,65 6095,70 6375,70 6375,110 6885,930 6885,960 6885,990 6885,1020 2575,1415 3965,1415 5355,1415
+15V_U_HS: C59.1 C67.1 U15.5 U18.7
  other v1: 2030,2715 2030,2745
  other v2: 1760,2855 1810,2855
+15V_U_LS: C79.1 C85.1 U20.5 U22.7
  other v1: 2035,1965 2035,1995
  other v2: 1760,2105 1810,2105
+15V_V_HS: C36.1 C42.1 U9.5 U12.7
  other v1: 2035,3465 2035,3495
  other v2: 1760,3605 1810,3605
+15V_V_LS: C74.1 C86.1 U21.5 U23.7
  other v1: 4970,1965 4970,1995
  other v2: 5240,2342.8 5185,2345
+15V_W_HS: C29.1 C43.1 U10.5 U13.7
  other v1: 4970,3465 4970,3495
  other v2: 5185,3830 5240,3830
+15V_W_LS: C52.1 C68.1 U17.5 U19.7
  other v1: 4970,2715 4970,2745
  other v2: 5240,3092.8 5185,3095
-3V_U_HS: C51.2 C65.2 U15.8 U18.5
  other v1: 2035,2800 2035,2830
  other v2: 1760,3092.8 1820,3092.8
-3V_U_LS: C73.2 C83.2 U20.8 U22.5
  other v1: 2035,2050 2035,2080
  other v2: 1760,2342.8 1820,2342.8
-3V_V_HS: C28.2 C40.2 U9.8 U12.5
  other v1: 2035,3550 2035,3580
  other v2: 1760,3845 1815,3845
-3V_V_LS: C80.2 C84.2 U21.8 U23.5
  other v1: 4970,2050 4970,2080
  other v2: 5185,2115 5240,2117.2
-3V_W_HS: C37.2 C41.2 U10.8 U13.5
  other v1: 4970,3550 4970,3580
  other v2: 5185,3615 5240,3617.2
-3V_W_LS: C60.2 C66.2 U17.8 U19.5
  other v1: 4970,2800 4970,2830
  other v2: 5185,2865 5240,2867.2
-15V: C162.2 C163.2 C164.2 C190.1 C191.1 C192.1 C193.1 C199.1 C200.1 C201.1 C202.1 D7.1 L8.2 TP9.1 U26.7 U27.7 U28.7 | length 1226.3
  Top Layer w10: v1(5695,80) 5737.99,80 L8.2@5792.99,135 ; v1(5695,135) L8.2@5792.99,135 ; v1(5695,190) 5737.99,190 L8.2@5792.99,135 ; v1(5750,1090) 6010,1090 6090,1170 D7.1@6603.66,1170
  other v1: 5595,80 5645,105 5595,135 5645,165 5595,190 5900,195 5930,195 5970,195 6000,195 5690,1090 5720,1090 5730,1190 5765,1190 2495,1290 3885,1290 5275,1290
A0: R50.2 U5.9 | length 357.8
  Top Layer w10: U5.9@6933.07,4541.14 6937.91,4545.98 6955.44,4545.98 6986.6,4577.15 6986.6,4635.82 7038.75,4687.97 7141.13,4687.97 7179.09,4650 R50.2@7180,4650
A1: R49.2 U5.11 | length 186.2
  Top Layer w10: R49.2@6818.62,4634 6819.53,4634 6832.48,4621.04 6832.48,4620.14 6851.5,4601.12 6851.5,4567.48 6904.49,4514.49 6914.45,4514.49 6919.29,4509.65 U5.11@6933.07,4509.65
BLEED1: R1.1 R2.2 R5.1 R6.2 R9.1 R10.2 | length 914.5
  Top Layer w30: R9.1@3014.25,7250 3100,7250 ; R5.1@3014.25,7450 3100,7450 ; R1.1@3014.25,7650 3100,7650 ; R10.2@3185.75,7250 3100,7250 ; R6.2@3185.75,7450 3100,7450 ; R2.2@3185.75,7650 3100,7650 ; 3100,7250 3100,7450 ; 3100,7450 3100,7650
BLEED2: R2.1 R3.2 R6.1 R7.2 R10.1 R11.2 | length 914.5
  Top Layer w30: R10.1@3414.25,7250 3500,7250 ; R6.1@3414.25,7450 3500,7450 ; R2.1@3414.25,7650 3500,7650 ; R11.2@3585.75,7250 3500,7250 ; R7.2@3585.75,7450 3500,7450 ; R3.2@3585.75,7650 3500,7650 ; 3500,7250 3500,7450 ; 3500,7450 3500,7650
BLEED3: R3.1 R4.2 R7.1 R8.2 R11.1 R12.2 | length 914.5
  Top Layer w30: R11.1@3814.25,7250 3900,7250 ; R7.1@3814.25,7450 3900,7450 ; R3.1@3814.25,7650 3900,7650 ; R12.2@3985.75,7250 3900,7250 ; R8.2@3985.75,7450 3900,7450 ; R4.2@3985.75,7650 3900,7650 ; 3900,7250 3900,7450 ; 3900,7450 3900,7650
CAN_H: C121.1 J4.7 J5.2 L10.2 R193.2 R194.2 | length 1521.7
  Bottom Layer w8: J5.2@7315,5325 7550.61,5089.35 7550.61,5089.06 7555.29,5084.37 7596.96,5084.37 7635.78,5045.55 7635.78,5015.6 J4.7@7680.49,4970.89
  Bottom Layer w10: J4.7@7680.49,4970.89 J4.7@7685.91,4965.47 7735,5014.57 7735,5081.53 7775.47,5122 R194.2@7776.38,5122 R193.2@7776.38,5190 7777.28,5190 7807.28,5220 7855.99,5220 7870,5205.99 7870,4765 7864.39,4759.39 7864.39,4758.58 ; C121.1@7776.42,4782 7777.37,4782 7807.24,4752.14 7857.95,4752.14 7864.39,4758.58 ; L10.2@7894.57,4719.21 7885.71,4719.21 7872.99,4731.93 7872.99,4749.98 7864.39,4758.58
CAN_HFILT: L10.1 U36.7 | length 769
  Top Layer w10: v1(7930,4465) 7932.5,4462.5 7932.5,4112.5 v1(7935,4110)
  Bottom Layer w10: L10.1@7715.43,4719.21 7724.29,4719.21 7737.01,4706.5 7737.01,4697.64 7930,4504.65 v1(7930,4465) ; U36.7@7881.71,4085 7909.36,4085 7934.36,4110 v1(7935,4110)
CAN_L: C120.2 J4.2 J5.3 L10.3 R195.1 R196.1 | length 1248.2
  Bottom Layer w8: J5.3@7325,5235 7376.67,5235 7546.67,5065 7590.87,5065 7617.78,5038.09 7617.78,4951.21 7577.52,4910.94 J4.2@7574.09,4910.94
  Bottom Layer w10: J5.3@7315,5225 J5.3@7325,5235 ; J4.2@7574.09,4910.94 7700.42,4910.94 ; C120.2@7776.42,4850 C120.2@7775.47,4850 ; R195.1@7776.38,5054 R196.1@7776.38,4986 7775.47,4986 7700.42,4910.94 ; L10.3@7894.57,4620.79 7885.71,4620.79 7756.5,4750 7755,4750 7752.86,4752.14 7752.05,4752.14 7745.61,4758.58 7745.61,4820.14 C120.2@7775.47,4850 ; 7700.42,4910.94 7714.53,4910.94 C120.2@7775.47,4850
CAN_LFILT: L10.4 U36.6 | length 660.2
  Bottom Layer w10: L10.4@7715.43,4620.79 7724.65,4630 7776.36,4630 7901.5,4504.86 7901.5,4453.19 7931.18,4423.52 7931.18,4157.46 7908.72,4135 U36.6@7881.71,4135
CAN_MIDC: C119.2 C120.1 C121.2 | length 140
  Bottom Layer w10: C121.2@7833.58,4782 C120.1@7833.58,4850 C119.2@7833.58,4922
CAN_MIDR: C119.1 R193.1 R194.1 R195.2 R196.2 | length 292.8
  Bottom Layer w10: C119.1@7776.42,4922 7777.37,4922 7791.24,4935.86 7791.24,4944.52 7832.72,4986 R196.2@7833.62,4986 R195.2@7833.62,5054 R194.1@7833.62,5122 R193.1@7833.62,5190
CAN_RX: U5.87 U36.3 | length 1232.6
  Top Layer w10: U5.87@6933.07,3186.81 6969.14,3186.81 6975,3192.67 6975,3265.21 6980,3270.21 v1(6980,3330)
  Bottom Layer w10: v1(6980,3330) 6980,3391.57 7335,3746.57 7335,3840 7395,3900 7395,4090 7440,4135 U36.3@7493.29,4135
CAN_TX: U5.88 U36.2 | length 1186.5
  Top Layer w10: v1(7014.98,3238.12) 7018.24,3234.87 7018.24,3217.98 7038.75,3197.46 7042.5,3197.46 7053.15,3186.81 U5.88@7066.93,3186.81
  Bottom Layer w10: v1(7014.98,3238.12) 7014.57,3238.12 6989.5,3263.19 6989.5,3286.81 7010,3307.31 7010,3393.28 7360,3743.28 7360,3830 7415,3885 7415,4070 7430,4085 U36.2@7493.29,4085
COS: C23.1 R62.2 U5.34 | length 177.7
  Top Layer w10: U5.34@7066.93,4163.19 C23.1@7176.61,4163.19 ; R62.2@7181.38,4100 7181.38,4167.96 C23.1@7181.42,4168
COS_N: C176.2 D10.6 J17.6 R268.1 R269.1 | length 1079.9
  Top Layer w8: 7528.27,673.3 7547.3,654.27 7587.84,654.27 7601.48,640.63 7625,640.63 7690,705.63 7690,785 7740.5,835.5 7814.5,835.5 J17.6@7860,790
  Top Layer w10: D10.6@7524.41,699.37 7524.41,685.59 7528.27,681.73 7528.27,673.3
  Bottom Layer w8: R269.1@7688,716.38 7786.38,716.38 J17.6@7860,790
  Bottom Layer w10: R268.1@7558.62,771 7636.02,771 7638.59,773.58 7644.89,773.58 7650.75,779.43 7650.75,797.62 7656.61,803.48 7707.73,803.48 7740.74,836.5 7813.5,836.5 J17.6@7860,790
COS_P: C176.1 D10.3 J17.5 R269.2 R271.1 | length 520.5
  Top Layer w10: D10.3@7575.59,620.63 7633.11,620.63 7755.98,743.5 7755.98,785.98 J17.5@7760,790
  Bottom Layer w10: R271.1@7558.62,703 7608.58,703 7622,716.42 7622,717.37 7635.86,731.24 7648.52,731.24 7690,772.72 R269.2@7690,773.62 ; R269.2@7688,773.62 7688,774.53 7696.96,783.48 7753.48,783.48 J17.5@7760,790
DC+: C110.1 C110.2 C111.1 C111.2 C112.1 C112.2 J2.1 J2.2 J2.3 J2.4 J2.5 J2.6 J2.7 J2.8 Q2.DC+_1 Q2.DC+_2 Q2.DC+_3 R1.2 R5.2 R9.2 R13.1 TP1.1 TP2.1 | length 1654.8
  Top Layer w10: 5749.61,6803.46 5749.61,7079.61 5875,7205 6325,7205 6325.12,7205.12 R13.1@6580,7205.12
  Top Layer w30: v2(2725,7500) 2730.41,7500 2751.32,7479.09 2781.89,7479.09 2785.75,7475.23 R5.2@2785.75,7450 ; R9.2@2785.75,7250 R5.2@2785.75,7450 ; R1.2@2785.75,7650 R5.2@2785.75,7450
DC+1: R13.2 R17.1 | length 79.8
  Top Layer w10: R17.1@6580,7015.12 R13.2@6580,7094.88
DC+2: R17.2 R21.1 | length 79.8
  Top Layer w10: R21.1@6580,6825.12 R17.2@6580,6904.88
DC+3: R21.2 R25.1 | length 79.8
  Top Layer w10: R25.1@6580,6635.12 R21.2@6580,6714.88
DC+4: R25.2 R29.1 | length 79.8
  Top Layer w10: R29.1@6580,6445.12 R25.2@6580,6524.88
DC+5: R29.2 R33.1 | length 79.8
  Top Layer w10: R33.1@6580,6255.12 R29.2@6580,6334.88
DC-: C110.3 C110.4 C111.3 C111.4 C112.3 C112.4 J3.1 J3.2 J3.3 J3.4 J3.5 J3.6 J3.7 J3.8 Q2.DC-1 Q2.DC-2 Q2.DC-3 R4.1 R8.1 R12.1 R160.1 TP3.1 TP4.1 | length 2171.4
  Top Layer w10: J3.4@5040,7550 5395,7550 5555,7390 v1(6105,7390)
  Top Layer w30: R12.1@4214.25,7250 R8.1@4214.25,7450 ; R4.1@4214.25,7650 R8.1@4214.25,7450 ; v2(4265,7500) 4248.11,7483.11 4218.11,7483.11 4214.25,7479.25 R8.1@4214.25,7450
  Bottom Layer w10: v1(6105,7390) 6289.88,7205.12 R160.1@6580,7205.12
DC-1: R160.2 R164.1 | length 79.8
  Bottom Layer w10: R164.1@6580,7015.12 R160.2@6580,7094.88
DC-2: R164.2 R168.1 | length 79.8
  Bottom Layer w10: R168.1@6580,6825.12 R164.2@6580,6904.88
DC-3: R168.2 R172.1 | length 79.8
  Bottom Layer w10: R172.1@6580,6635.12 R168.2@6580,6714.88
DC-4: R172.2 R176.1 | length 79.8
  Bottom Layer w10: R176.1@6580,6445.12 R172.2@6580,6524.88
DC-5: R176.2 R180.1 | length 79.8
  Bottom Layer w10: R180.1@6580,6255.12 R176.2@6580,6334.88
EPWM7A: R76.2 U5.58 | length 124.7
  Top Layer w10: U5.58@7066.93,3659.25 7155.72,3659.25 7180.47,3684 R76.2@7181.38,3684
EPWM7B: R82.2 U5.60 | length 166
  Top Layer w10: U5.60@7066.93,3627.76 7132.24,3627.76 7150,3610 7150,3578.47 7180.47,3548 R82.2@7181.38,3548
EXC_N: C167.2 D8.3 J17.2 R249.2 U39.9 | length 1314.3
  Top Layer w10: D8.3@7575.59,980.63 7579.4,980.63 7594.36,980.63 7614.99,960 7685.31,960 7704.55,979.24 7704.55,1018.75 7725.79,1040 7810,1040 J17.2@7860,990
  Bottom Layer w10: C167.2@7171.42,1126 R249.2@7171.38,1194 R249.2@7171.38,1194 7184.33,1206.96 7185.24,1206.96 7250.13,1271.84 7468.16,1271.84 7530,1210 7587.99,1210 7594.7,1203.29 7594.7,1169.5 7585.24,1160.04 7614.96,1160.04 7738.5,1036.5 7813.5,1036.5 J17.2@7860,990
EXC_P: C93.2 D8.6 J17.1 R143.2 U39.13 | length 932.7
  Top Layer w10: R143.2@7348.62,1022 C93.2@7348.58,1091 C93.2@7348.58,1091 7356.42,1098.84 7356.42,1186.47 7386.4,1216.46 7493.6,1216.46 7520,1190.05 7520,1190 7524.41,1185.59 7524.41,1060 7528.27,1056.14 7528.27,1034.05 7548.05,1014.27 7589.01,1014.27 7606.45,996.82 7631.81,996.82 7651.75,1016.76 7651.75,1036.75 v1(7655,1040) v1@7656.81,1038.19 ; J17.1@7751.5,998.5 J17.1@7760,990
  Bottom Layer w10: U39.13@7554.17,1053.82 7636.58,1053.82 7650.4,1040 v1(7655,1040) 7658.25,1036.75 7708.25,1036.75 7728.5,1016.5 7733.5,1016.5 J17.1@7760,990
FAN1: R242.1 U38.16 | length 231.3
  Bottom Layer w10: U38.16@7462.2,2792.2 7585.17,2792.2 7647.52,2729.86 7647.52,2728.96 7660.47,2716 R242.1@7661.38,2716
FAN1_OUT: R240.1 U5.105 U38.4 | length 551.6
  Top Layer w10: U5.105@6947.25,2903.75 6951.69,2908.19 6955.44,2908.19 6980.43,2933.18 6980.43,2960.83 v1(6980.99,2961.39)
  Bottom Layer w10: v1(6980.99,2961.39) 6980.99,2956.79 6971.52,2947.32 6971.52,2830.49 6977.96,2824.04 7028.76,2824.04 7057.72,2853 R240.1@7058.62,2853 ; R240.1@7058.62,2855 7123.21,2855 7145,2833.21 7145,2789.78 7168.16,2766.61 U38.4@7237.8,2766.61
FAN2: R241.1 U38.15 | length 213.2
  Bottom Layer w10: U38.15@7462.2,2817.8 7592.2,2817.8 7623.38,2786.63 7658.75,2786.63 R241.1@7661.38,2784
FAN2_OUT: R239.1 U5.107 U38.5 | length 524.2
  Top Layer w10: U5.107@6933.07,2871.85 6937.91,2876.69 6955.44,2876.69 6961.25,2882.5 7020,2941.25 7020,2968.15 7013.25,2974.9 v1(7013.25,2979.5)
  Bottom Layer w10: v1(7013.25,2979.5) 7015.5,2981.75 7038.25,2981.75 7060,2960 R239.1@7060,2920 7062.1,2917.9 7062.1,2892.9 7073.04,2881.96 7104.46,2881.96 7111.41,2875 7131.49,2875 7165,2841.49 7165,2798.06 7170.86,2792.2 U38.5@7237.8,2792.2
FB_15V: C98.2 R142.2 R144.1 U29.9 | length 258.8
  Top Layer w8: R144.1@6182.24,980 6182.24,1043.62 R142.2@6183.62,1045 ; R144.1@6183.62,980 C98.2@6183.58,913 6222,913 6271.52,863.48 6271.52,860.18 6272.18,859.53 U29.9@6285.77,859.53
G1: J6.1 Q2.G1 R94.2 R97.2 R105.2 | length 412.6
  Top Layer w10: J6.1@2900.39,3800 2900.39,3589.61 2930,3560 2931.48,3560 2932.86,3558.62 3006.38,3558.62 3025,3540 3025,3520 3008.94,3503.94 Q2.G1@2996.06,3503.94 Q2.G1@2995,3505
G1H: R105.1 U15.6
G1L: R97.1 U15.7
G2: J13.1 Q2.G2 R120.2 R123.2 R131.2 | length 308.6
  Top Layer w10: Q2.G2@2870.08,2496.06 2870.08,2493.05 2900.39,2462.74 J13.1@2900.39,2200
G2H: R131.1 U20.6
G2L: R123.1 U20.7
G3: J7.1 Q2.G3 R64.2 R67.2 R74.2 | length 395.2
  Top Layer w10: Q2.G3@3374.02,3503.94 3378.94,3503.94 3420,3545 3420,3721.48 3408.62,3732.86 3408.62,3767.14 3441.48,3800 J7.1@3500.39,3800
G3H: R74.1 U9.6
G3L: R67.1 U9.7
G4: J14.1 Q2.G4 R121.2 R124.2 R132.2 | length 370.6
  Top Layer w10: J14.1@3500.39,2200 3500.39,2408.91 3580.98,2489.5 3619.42,2489.5 Q2.G4@3625.98,2496.06
G4H: R124.1 U21.6
G4L: R132.1 U21.7
G5: J8.1 Q2.G5 R65.2 R68.2 R75.2 | length 691.7
  Top Layer w10: Q2.G5@3751.97,3503.94 3706.06,3503.94 3690,3520 3690,3685 3770,3765 3995,3765 4030,3800 J8.1@4100.39,3800
G5H: R68.1 U10.6
G5L: R75.1 U10.7
G6: J15.1 Q2.G6 R95.2 R98.2 R106.2 | length 308.3
  Top Layer w10: J15.1@4100.39,2200 4100.39,2461.95 4129.92,2491.48 Q2.G6@4129.92,2496.06
G6H: R98.1 U17.6
G6L: R106.1 U17.7
GD_DIS: R83.1 U5.74 | length 428.3
  Top Layer w10: R83.1@6830,3491.38 R83.1@6818.62,3480 6819.53,3480 6846.27,3506.75 6856.75,3506.75 v1(6860,3510) ; v1(7015,3555) 7015,3505.05 7020,3500.05 7020,3427.61 7035.48,3412.13 7062.09,3412.13 U5.74@7066.93,3407.28
  Bottom Layer w10: v1(6860,3510) 6900.81,3510 6945.81,3555 v1(7015,3555)
GD_DIS_FILT: C146.1 R83.2 R220.2 U11.1 U11.19 | length 465.8
  Top Layer w10: U11.19@6510.59,3589.41 6555.59,3589.41 6581.18,3563.82 6750.75,3563.82 v1@6766.31,3548.25 ; R83.2@6761.38,3480 6761.38,3526.78 6775,3540.4 v1(6775,3545)
  Bottom Layer w10: C146.1@6746.42,3509.05 6771.75,3534.37 6771.75,3541.75 v1(6775,3545) v1@6775,3540.4 ; R220.2@6756.38,3430 C146.1@6756.42,3500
